(* Logix 5000 project; controller Example_PLC vendor 1 type 14 code 77 rev 19.11; software revision 19.01 *)

TASK MainTask (continuous, watchdog 500 ms) : MainProgram

MODULES
   Controller : vendor 1 type 14 code 77 (CompactLogixL32EController 0, rev 19.11)
      LocalENB : 1769-L32E Ethernet Port (CompactLogixL32Ethernet 1, Ethernet 10.8.46.172, rev 19.11)
         AKD_1 : ETHERNET-MODULE (Ethernet 10.8.46.173, rev 1.1, Output RPI 40 ms)
         AKD_2 : ETHERNET-MODULE (Ethernet 10.8.46.174, rev 1.1, Output RPI 40 ms)
      Local : CompactBus (CompactVirtualAdapter 3, rev 19.11)
END_MODULES

TYPE AKD_Axis :   // Axis Data:
STRUCT
   Control : AKD_Control;   // Control bits to send to the drive
   Status : AKD_Status;   // Status bits received from the drive
   Input : AB:ETHERNET_MODULE_SINT_64Bytes:I:0;   // Data from the drive
   Output : AB:ETHERNET_MODULE_SINT_64Bytes:O:0;   // Data to the drive
   ResponseMsgType : SINT;   // Response type contained in latest IO response from drive. Used to check for errors
   CommandTimeout : INT;   // Time to allow for command response from drive. Dependent on scan rate and communicaiton rate
   PositionFeedback : DINT;   // Actual Position Value
   VelocityFeedback : DINT;   // Actual Velocity Value
END_STRUCT
END_TYPE

TYPE AKD_Control :   // Send Explicit Message
STRUCT
   Load_Data_Start_Profile : BOOL;   // Load Command Data / Start Profile Move
   Start_Block : BOOL;   // Execute Command block or block chain
   Incremental : BOOL;   // Incremental Position (0=Absolute, 1=Incremental)
   Direction : BOOL;   // Direction in Velocity Mode (0=Reverse, 1=Forward)
   Smooth_Stop : BOOL;   // Smooth / Controlled Stop w/ Deceleration
   Hard_Stop : BOOL;   // Hard / Immediate Stop
   Reg_Arm : BOOL;   // Arm the Registration Input
   Enable : BOOL;   // Enable Output
END_STRUCT
END_TYPE

TYPE AKD_Status :   // All connections to the drive ethernet module are established and data is successfully transferring.
STRUCT
   Profile_In_Progress : BOOL;   // Profile Move In Progress
   Block_In_Execution : BOOL;   // Block In Execution
   On_Target_Position : BOOL;   // On Target Position (1=Current Position Equals Last Target Position)
   General_Fault : BOOL;   // General Fault
   Current_Direction : BOOL;   // Current Motor Direction (0=Reverse, 1=Forward)
   Home_Level : BOOL;   // Level of Home Input
   Reg_Level : BOOL;   // Level of Registration Input
   Enable : BOOL;   // State of Enable Output
   Fault_Input_Fault : BOOL;   // Fault Input Active
   Fwd_Limit : BOOL;   // Forward Input Active
   Rev_Limit : BOOL;   // Reverse Input Active
   Positive_Limit : BOOL;   // Positive Software Limit Exceeded
   Negative_Limit : BOOL;   // Negative Software Limit Exceeded
   FE_Fault : BOOL;   // Following Error Fault
   Block_Fault : BOOL;   // Block Execution Fault
   Load_Complete : BOOL;   // Command Message Successfully Loaded
END_STRUCT
END_TYPE

TYPE Motion_Task :
STRUCT
   Accel : LINT;   // MT.ACC Acceleration
   ControlWord : DINT;   // MT.CNTL
   Decel : LINT;   // MT.DEC
   Delay : INT;   // MT.TNEXT Delay before executing next task
   NextNum : SINT;   // MT.TNEXT Number of next task to execute
   Position : LINT;   // MT.P Target Position
   Num : SINT;   // MT.NUM Number of this task in the table
   Velocity : LINT;   // MT.V Target Velocity
   Set : SINT;   // Used to command a set of the MT. Should always equal 1
END_STRUCT
END_TYPE

ADD_ON_INSTRUCTION AKD_Disable   (* revision 2.1, ExecutePrescan, ExecuteEnableInFalse *)
// Disable Drive
// Revision note:
// Don't error if Command_Timeout preset is 0
VAR_OUTPUT
   DN : BOOL; {access Read Only, visible}   // Command Successful
   ER : BOOL; {access Read Only, visible}   // Error
END_VAR
VAR_IN_OUT
   Axis : AKD_Axis; {required}
END_VAR
VAR
   Command_Timeout : TIMER := (PRE := 200);   // Timeout Timer
END_VAR

ROUTINE EnableInFalse   (* ladder *)
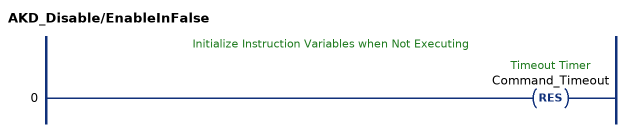
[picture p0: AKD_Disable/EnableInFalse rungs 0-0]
   // Initialize Instruction Variables when Not Executing
   0: RES(Command_Timeout);
END_ROUTINE

ROUTINE Logic   (* ladder *)
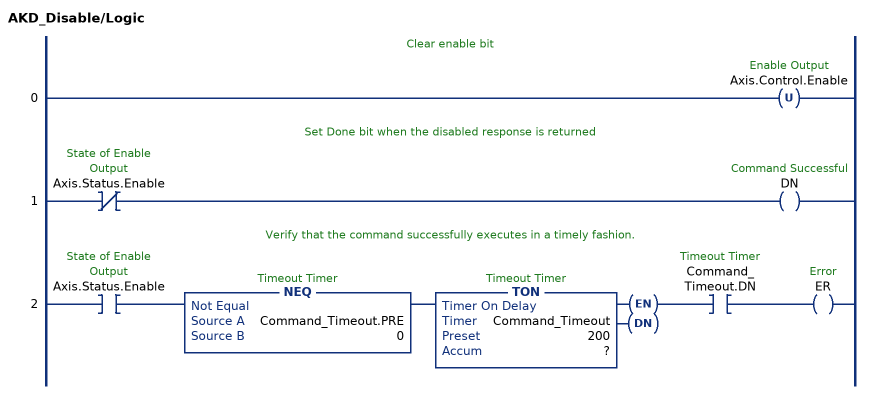
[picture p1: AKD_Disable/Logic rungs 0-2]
   // Clear enable bit
   0: OTU(Axis.Control.Enable);
   // Set Done bit when the disabled response is returned
   1: XIO(Axis.Status.Enable)OTE(DN);
   // Verify that the command successfully executes in a timely fashion.
   2: XIC(Axis.Status.Enable)NEQ(Command_Timeout.PRE,0)TON(Command_Timeout,?,?)XIC(Command_Timeout.DN)OTE(ER);
END_ROUTINE

ROUTINE Prescan   (* ladder *)
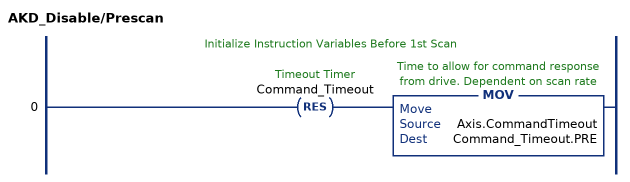
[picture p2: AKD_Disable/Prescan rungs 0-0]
   // Initialize Instruction Variables Before 1st Scan
   0: RES(Command_Timeout)MOV(Axis.CommandTimeout,Command_Timeout.PRE);
END_ROUTINE
END_ADD_ON_INSTRUCTION

ADD_ON_INSTRUCTION AKD_Drive   (* revision 2.0, ExecutePrescan *)
// Drive Communication
VAR_IN_OUT
   Axis_Input : AB:ETHERNET_MODULE_SINT_64Bytes:I:0; {required}
   Axis_Output : AB:ETHERNET_MODULE_SINT_64Bytes:O:0; {required}
   Axis_Internal : AKD_Axis; {required}
END_VAR
VAR
   Command_Bytes : SINT[8];
   Response_Bytes : SINT[8];
END_VAR

ROUTINE Logic   (* ladder *)
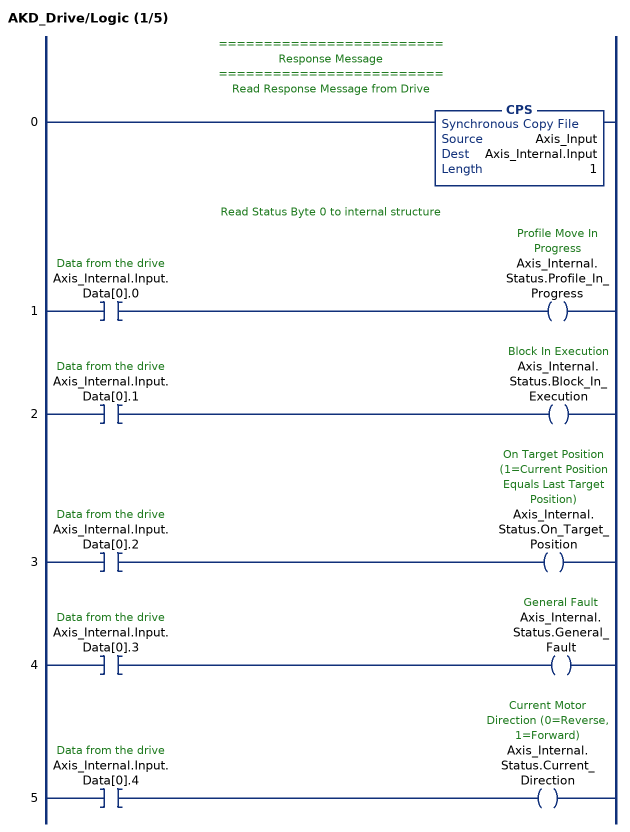
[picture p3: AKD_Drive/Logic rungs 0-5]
   // =========================
   // Response Message
   // =========================
   // Read Response Message from Drive
   0: CPS(Axis_Input,Axis_Internal.Input,1);
   // Read Status Byte 0 to internal structure
   1: XIC(Axis_Internal.Input.Data[0].0)OTE(Axis_Internal.Status.Profile_In_Progress);
   2: XIC(Axis_Internal.Input.Data[0].1)OTE(Axis_Internal.Status.Block_In_Execution);
   3: XIC(Axis_Internal.Input.Data[0].2)OTE(Axis_Internal.Status.On_Target_Position);
   4: XIC(Axis_Internal.Input.Data[0].3)OTE(Axis_Internal.Status.General_Fault);
   5: XIC(Axis_Internal.Input.Data[0].4)OTE(Axis_Internal.Status.Current_Direction);
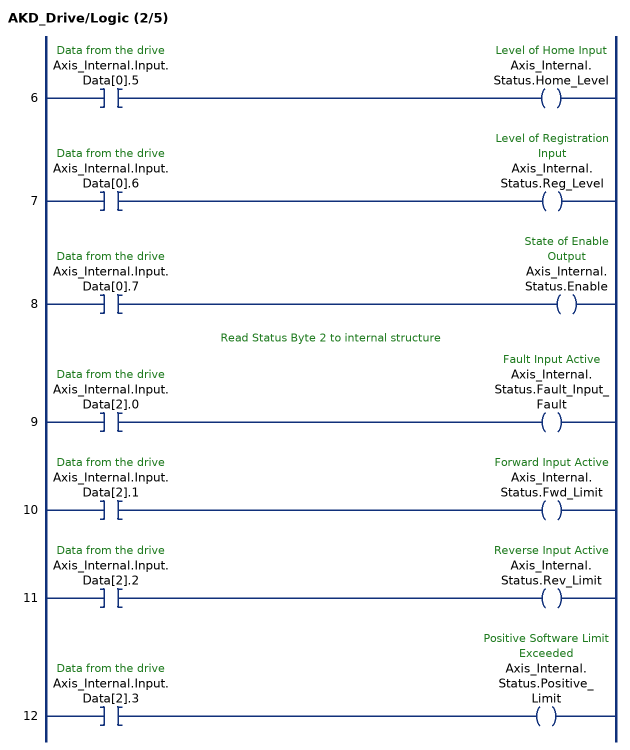
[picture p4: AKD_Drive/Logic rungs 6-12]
   6: XIC(Axis_Internal.Input.Data[0].5)OTE(Axis_Internal.Status.Home_Level);
   7: XIC(Axis_Internal.Input.Data[0].6)OTE(Axis_Internal.Status.Reg_Level);
   8: XIC(Axis_Internal.Input.Data[0].7)OTE(Axis_Internal.Status.Enable);
   // Read Status Byte 2 to internal structure
   9: XIC(Axis_Internal.Input.Data[2].0)OTE(Axis_Internal.Status.Fault_Input_Fault);
   10: XIC(Axis_Internal.Input.Data[2].1)OTE(Axis_Internal.Status.Fwd_Limit);
   11: XIC(Axis_Internal.Input.Data[2].2)OTE(Axis_Internal.Status.Rev_Limit);
   12: XIC(Axis_Internal.Input.Data[2].3)OTE(Axis_Internal.Status.Positive_Limit);
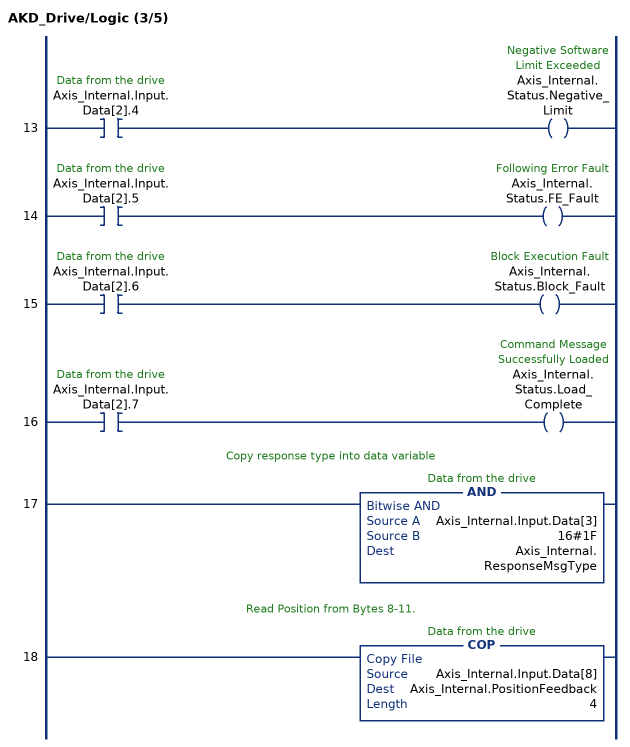
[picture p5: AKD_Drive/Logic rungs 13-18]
   13: XIC(Axis_Internal.Input.Data[2].4)OTE(Axis_Internal.Status.Negative_Limit);
   14: XIC(Axis_Internal.Input.Data[2].5)OTE(Axis_Internal.Status.FE_Fault);
   15: XIC(Axis_Internal.Input.Data[2].6)OTE(Axis_Internal.Status.Block_Fault);
   16: XIC(Axis_Internal.Input.Data[2].7)OTE(Axis_Internal.Status.Load_Complete);
   // Copy response type into data variable
   17: AND(Axis_Internal.Input.Data[3],16#1F,Axis_Internal.ResponseMsgType);
   // Read Position from Bytes 8-11.
   18: COP(Axis_Internal.Input.Data[8],Axis_Internal.PositionFeedback,4);
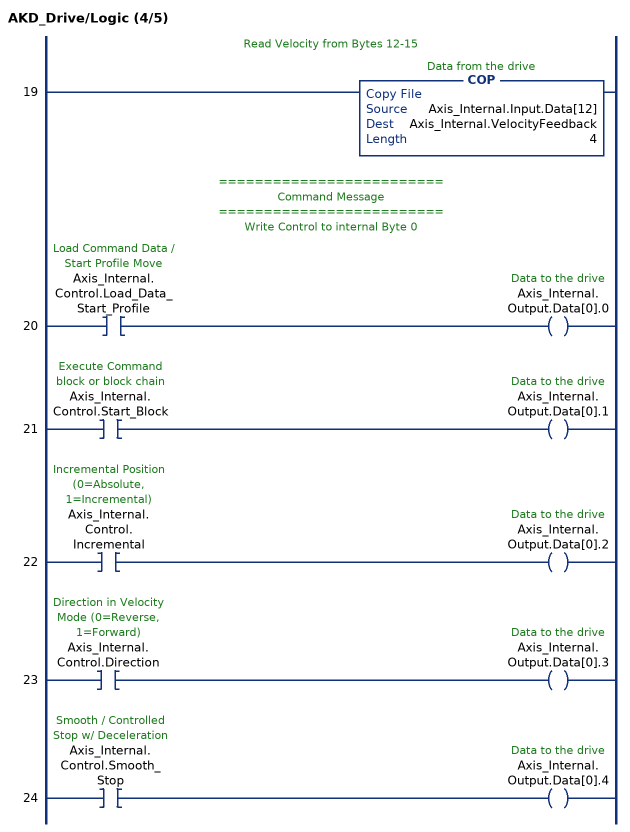
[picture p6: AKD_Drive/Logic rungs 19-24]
   // Read Velocity from Bytes 12-15
   19: COP(Axis_Internal.Input.Data[12],Axis_Internal.VelocityFeedback,4);
   // =========================
   // Command Message
   // =========================
   // Write Control to internal Byte 0
   20: XIC(Axis_Internal.Control.Load_Data_Start_Profile)OTE(Axis_Internal.Output.Data[0].0);
   21: XIC(Axis_Internal.Control.Start_Block)OTE(Axis_Internal.Output.Data[0].1);
   22: XIC(Axis_Internal.Control.Incremental)OTE(Axis_Internal.Output.Data[0].2);
   23: XIC(Axis_Internal.Control.Direction)OTE(Axis_Internal.Output.Data[0].3);
   24: XIC(Axis_Internal.Control.Smooth_Stop)OTE(Axis_Internal.Output.Data[0].4);
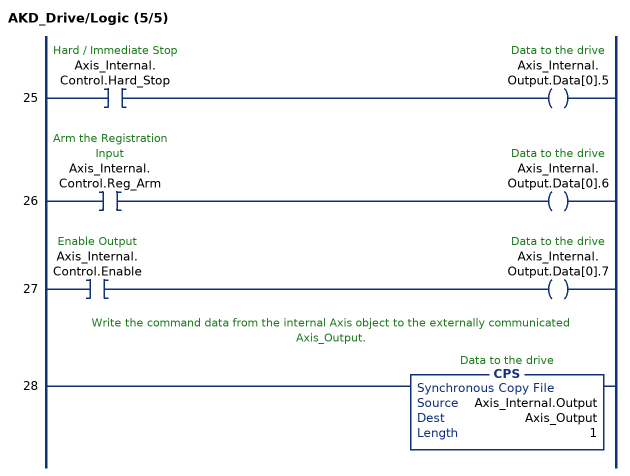
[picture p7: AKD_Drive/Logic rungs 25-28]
   25: XIC(Axis_Internal.Control.Hard_Stop)OTE(Axis_Internal.Output.Data[0].5);
   26: XIC(Axis_Internal.Control.Reg_Arm)OTE(Axis_Internal.Output.Data[0].6);
   27: XIC(Axis_Internal.Control.Enable)OTE(Axis_Internal.Output.Data[0].7);
   // Write the command data from the internal Axis object to the externally communicated Axis_Output.
   28: CPS(Axis_Internal.Output,Axis_Output,1);
END_ROUTINE

ROUTINE Prescan   (* ladder *)
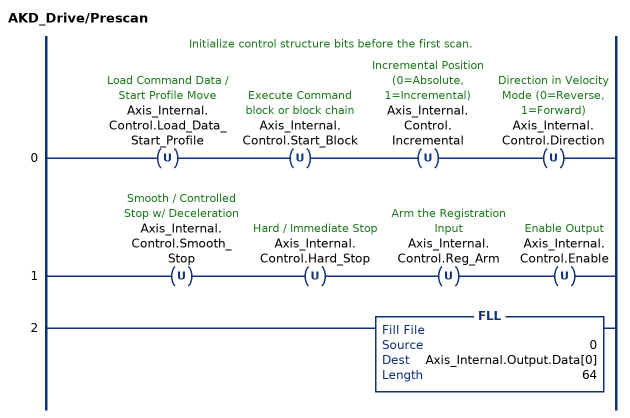
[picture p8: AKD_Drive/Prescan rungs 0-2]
   // Initialize control structure bits before the first scan.
   0: OTU(Axis_Internal.Control.Load_Data_Start_Profile)OTU(Axis_Internal.Control.Start_Block)OTU(Axis_Internal.Control.Incremental)OTU(Axis_Internal.Control.Direction);
   1: OTU(Axis_Internal.Control.Smooth_Stop)OTU(Axis_Internal.Control.Hard_Stop)OTU(Axis_Internal.Control.Reg_Arm)OTU(Axis_Internal.Control.Enable);
   2: FLL(0,Axis_Internal.Output.Data[0],64);
END_ROUTINE
END_ADD_ON_INSTRUCTION

ADD_ON_INSTRUCTION AKD_Enable   (* revision 2.0, ExecutePrescan, ExecuteEnableInFalse *)
// Enables Drive
VAR_OUTPUT
   DN : BOOL; {access Read Only, visible}   // Command Successful
   ER : BOOL; {access Read Only, visible}   // Error
END_VAR
VAR_IN_OUT
   Axis : AKD_Axis; {required}
END_VAR
VAR
   Command_Timeout : TIMER := (PRE := 2000);   // Timeout Timer
   Transition : BOOL;   // Marker to transition enable bit if required.
   Transition_Complete : BOOL;   // Flag to indicate that no further transistion is required.
END_VAR

ROUTINE EnableInFalse   (* ladder *)
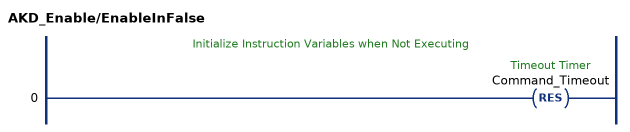
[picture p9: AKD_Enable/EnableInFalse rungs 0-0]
   // Initialize Instruction Variables when Not Executing
   0: RES(Command_Timeout);
END_ROUTINE

ROUTINE Logic   (* ladder *)
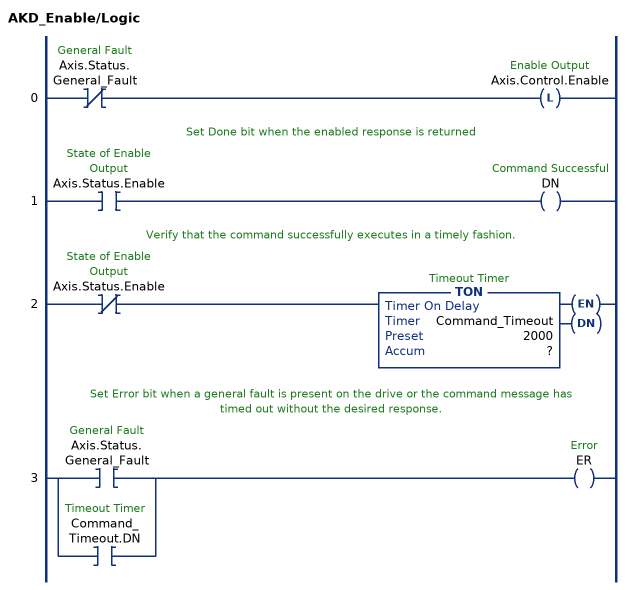
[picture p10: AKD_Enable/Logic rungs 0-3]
   0: XIO(Axis.Status.General_Fault)OTL(Axis.Control.Enable);
   // Set Done bit when the enabled response is returned
   1: XIC(Axis.Status.Enable)OTE(DN);
   // Verify that the command successfully executes in a timely fashion.
   2: XIO(Axis.Status.Enable)TON(Command_Timeout,?,?);
   // Set Error bit when a general fault is present on the drive or the command message has timed out without the desired response.
   3: [XIC(Axis.Status.General_Fault) ,XIC(Command_Timeout.DN) ]OTE(ER);
END_ROUTINE

ROUTINE Prescan   (* ladder *)
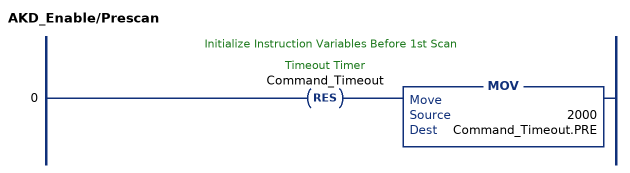
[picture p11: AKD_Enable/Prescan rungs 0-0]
   // Initialize Instruction Variables Before 1st Scan
   0: RES(Command_Timeout)MOV(2000,Command_Timeout.PRE);
END_ROUTINE
END_ADD_ON_INSTRUCTION

ADD_ON_INSTRUCTION AKD_Fault_Reset   (* revision 4.0, ExecutePrescan, ExecuteEnableInFalse *)
// Drive Fault Reset
// Revision note:
// Added logic to kill "enable" bit
VAR_OUTPUT
   DN : BOOL; {access Read Only, visible}   // Command Successful
   ER : BOOL; {access Read Only, visible}   // Error
END_VAR
VAR_IN_OUT
   Axis : AKD_Axis; {required}
END_VAR
VAR
   Step : SINT;
   Set_Parameter : AKD_Set_Parameter := (Parameter_Number := 113);
END_VAR

ROUTINE EnableInFalse   (* ladder *)
// EnableIn_False
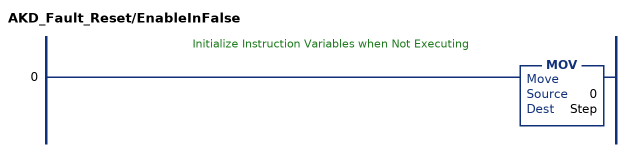
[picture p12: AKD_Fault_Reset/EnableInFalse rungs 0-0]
   // Initialize Instruction Variables when Not Executing
   0: MOV(0,Step);
END_ROUTINE

ROUTINE Logic   (* ladder *)
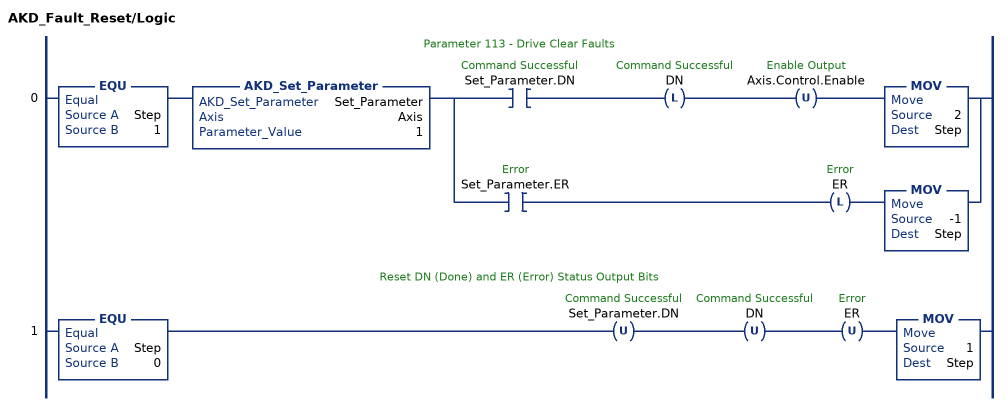
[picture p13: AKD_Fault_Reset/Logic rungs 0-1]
   // Parameter 113 - Drive Clear Faults
   0: EQU(Step,1)AKD_Set_Parameter(Set_Parameter,Axis,1)[XIC(Set_Parameter.DN) OTL(DN) OTU(Axis.Control.Enable) MOV(2,Step) ,XIC(Set_Parameter.ER) OTL(ER) MOV(-1,Step) ];
   // Reset DN (Done) and ER (Error) Status Output Bits
   1: EQU(Step,0)OTU(Set_Parameter.DN)OTU(DN)OTU(ER)MOV(1,Step);
END_ROUTINE

ROUTINE Prescan   (* ladder *)
// Prescan
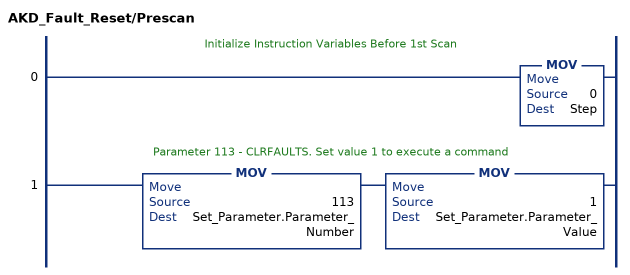
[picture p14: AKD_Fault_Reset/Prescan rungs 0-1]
   // Initialize Instruction Variables Before 1st Scan
   0: MOV(0,Step);
   // Parameter 113 - CLRFAULTS. Set value 1 to execute a command
   1: MOV(113,Set_Parameter.Parameter_Number)MOV(1,Set_Parameter.Parameter_Value);
END_ROUTINE
END_ADD_ON_INSTRUCTION

ADD_ON_INSTRUCTION AKD_Get_Attribute   (* revision 2.1, ExecutePrescan, ExecuteEnableInFalse *)
// Get Position Controller Attribute
// Revision note:
// Don't error if Command_Timeout preset is 0
VAR_OUTPUT
   DN : BOOL; {access Read Only, visible}   // Command Successful
   ER : BOOL; {access Read Only, visible}   // Error
END_VAR
VAR_IN_OUT
   Axis : AKD_Axis; {required}
END_VAR
VAR_INPUT
   Attribute_Number : INT; {visible}   // Attribute Number (see help for options)
END_VAR
VAR_OUTPUT
   Attribute_Value : DINT; {access Read Only, required}   // Attribute Value
END_VAR
VAR
   Command_Timeout : TIMER := (PRE := 100);   // Timeout Timer
   OS_LoadStart : BOOL;
   ErrorSource : SINT;
END_VAR

ROUTINE EnableInFalse   (* ladder *)
// EnableIn_False
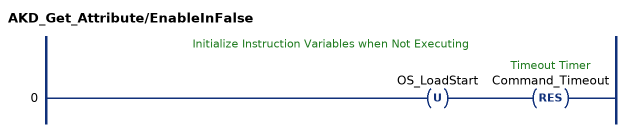
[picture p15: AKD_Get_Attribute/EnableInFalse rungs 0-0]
   // Initialize Instruction Variables when Not Executing
   0: OTU(OS_LoadStart)RES(Command_Timeout);
END_ROUTINE

ROUTINE Logic   (* ladder *)
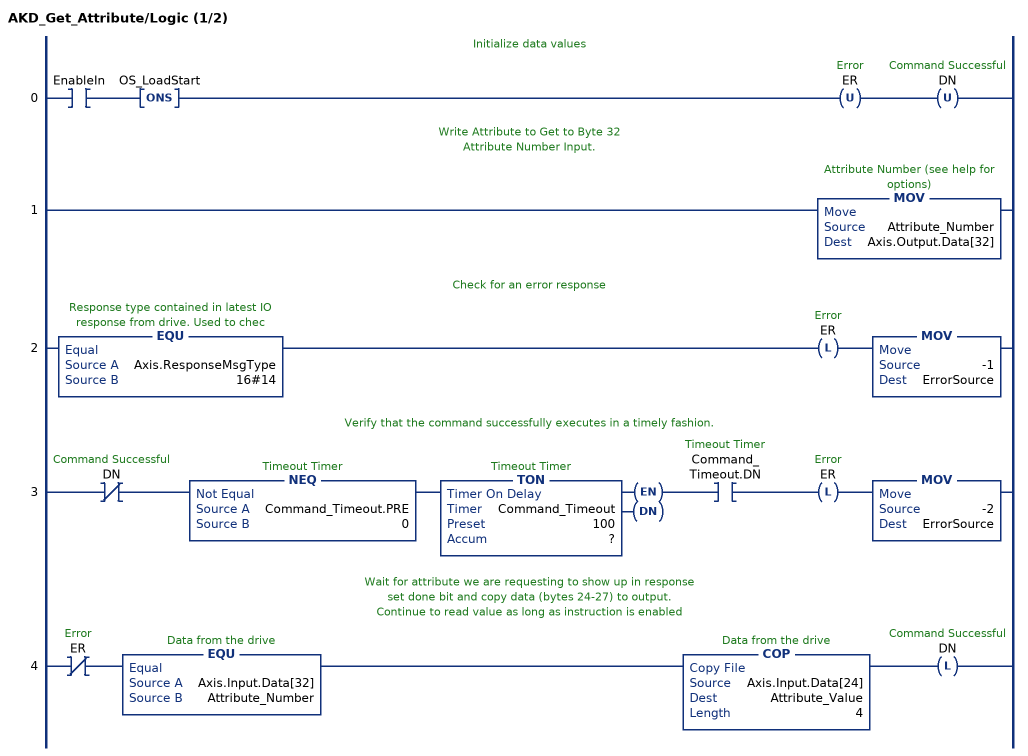
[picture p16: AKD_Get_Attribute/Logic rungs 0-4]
   // Initialize data values
   0: XIC(EnableIn)ONS(OS_LoadStart)OTU(ER)OTU(DN);
   // Write Attribute to Get to Byte 32
   // Attribute Number Input.
   1: MOV(Attribute_Number,Axis.Output.Data[32]);
   // Check for an error response
   2: EQU(Axis.ResponseMsgType,16#14)OTL(ER)MOV(-1,ErrorSource);
   // Verify that the command successfully executes in a timely fashion.
   3: XIO(DN)NEQ(Command_Timeout.PRE,0)TON(Command_Timeout,?,?)XIC(Command_Timeout.DN)OTL(ER)MOV(-2,ErrorSource);
   // Wait for attribute we are requesting to show up in response
   // set done bit and copy data (bytes 24-27) to output.
   // Continue to read value as long as instruction is enabled
   4: XIO(ER)EQU(Axis.Input.Data[32],Attribute_Number)COP(Axis.Input.Data[24],Attribute_Value,4)OTL(DN);
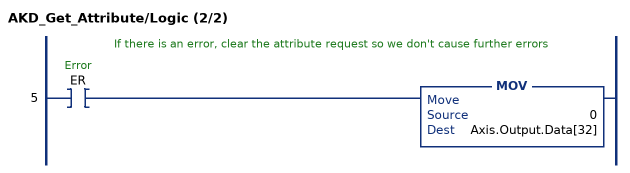
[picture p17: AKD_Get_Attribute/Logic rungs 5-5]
   // If there is an error, clear the attribute request so we don't cause further errors
   5: XIC(ER)MOV(0,Axis.Output.Data[32]);
END_ROUTINE
